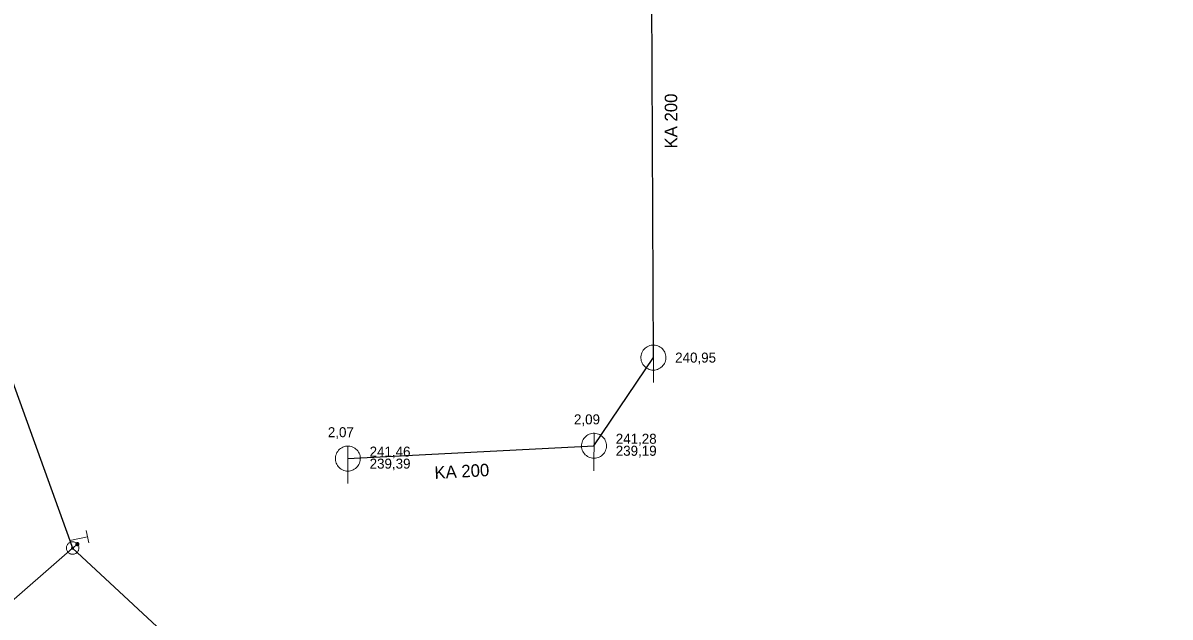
# Model space of a CAD drawing. Extents: x -777996 to -777727, y -976581 to -976199.
# Drawn here: x -777889.9 to -777798.1, y -976473.6 to -976426.1 of the extents above; entities that cross this region are included whole.
import ezdxf

# ---------------------------------------------------------------- set-up
doc = ezdxf.new("R2010")
doc.units = 0
doc.header["$LTSCALE"] = 0.32
doc.linetypes.add('MEDIUM_DASHED', pattern=[4.5, 3, -1.5])
for name, color, linetype, lineweight in [('1', 7, 'MEDIUM_DASHED', 25), ('13', 7, 'Continuous', 13), ('14', 7, 'Continuous', 25), ('17', 7, 'Continuous', 25), ('22', 7, 'Continuous', 13), ('34', 7, 'Continuous', 13), ('47', 7, 'Continuous', 13), ('9', 7, 'Continuous', 13)]:
    doc.layers.add(name, color=color, linetype=linetype, lineweight=lineweight)

msp = doc.modelspace()

# ---------------------------------------------------------------- linework, layer by layer
at = {"layer": '13'}
msp.add_line((-777885.941, -976468.086), (-777917.634, -976495.726), dxfattribs=at)
at = {"layer": '14'}
for p, q in [((-777839.462, -976452.855), (-777839.649, -976413.423)), ((-777844.215, -976459.905), (-777839.462, -976452.855)), ((-777863.916, -976460.934), (-777844.215, -976459.905))]:
    msp.add_line(p, q, dxfattribs=at)
at = {"layer": '14', "lineweight": 13}
for p, q in [((-777886.158, -976467.487), (-777884.76, -976467.18)), ((-777885.941, -976468.086), (-777885.559, -976467.772))]:
    msp.add_line(p, q, dxfattribs=at)
at = {"layer": '17'}
for points in [[(-777908.12, -976394.786), (-777900.403, -976428.079), (-777886.159, -976467.482), (-777885.941, -976468.086)], [(-777885.941, -976468.086), (-777876.204, -976477.129), (-777873.846, -976479.364), (-777871.717, -976481.385), (-777867.989, -976484.745), (-777854.131, -976495.614), (-777828.123, -976517.456), (-777820.88, -976521.51), (-777819.881, -976522.07), (-777768.129, -976539.208), (-777763.26, -976539.92)]]:
    msp.add_lwpolyline(points, dxfattribs=at)
at = {"layer": '22'}
for p, q in [((-777839.462, -976454.855), (-777839.461, -976451.855)), ((-777844.215, -976461.906), (-777844.214, -976458.906)), ((-777863.916, -976462.934), (-777863.915, -976459.934))]:
    msp.add_line(p, q, dxfattribs=at)
for points in [[(-777838.462, -976452.855), (-777838.467, -976452.746), (-777838.485, -976452.638), (-777838.515, -976452.532), (-777838.555, -976452.431), (-777838.607, -976452.334), (-777838.669, -976452.244), (-777838.741, -976452.161), (-777838.821, -976452.087), (-777838.909, -976452.021), (-777839.003, -976451.966), (-777839.103, -976451.921), (-777839.208, -976451.888), (-777839.315, -976451.866), (-777839.424, -976451.856), (-777839.534, -976451.858), (-777839.642, -976451.872), (-777839.749, -976451.897), (-777839.852, -976451.934), (-777839.95, -976451.983), (-777840.042, -976452.041), (-777840.128, -976452.11), (-777840.205, -976452.187), (-777840.274, -976452.273), (-777840.333, -976452.365), (-777840.381, -976452.463), (-777840.418, -976452.566), (-777840.444, -976452.673), (-777840.458, -976452.781), (-777840.461, -976452.891), (-777840.451, -976453), (-777840.43, -976453.107), (-777840.396, -976453.211), (-777840.352, -976453.311), (-777840.297, -976453.406), (-777840.231, -976453.494), (-777840.157, -976453.574), (-777840.074, -976453.646), (-777839.984, -976453.708), (-777839.888, -976453.76), (-777839.786, -976453.801), (-777839.681, -976453.831), (-777839.573, -976453.849), (-777839.463, -976453.855), (-777839.354, -976453.849), (-777839.246, -976453.831), (-777839.141, -976453.802), (-777839.039, -976453.761), (-777838.942, -976453.709), (-777838.852, -976453.647), (-777838.769, -976453.576), (-777838.694, -976453.496), (-777838.629, -976453.408), (-777838.573, -976453.314), (-777838.529, -976453.214), (-777838.495, -976453.11), (-777838.473, -976453.002), (-777838.463, -976452.893)], [(-777843.215, -976459.906), (-777843.22, -976459.797), (-777843.238, -976459.689), (-777843.268, -976459.583), (-777843.308, -976459.482), (-777843.36, -976459.385), (-777843.422, -976459.295), (-777843.494, -976459.212), (-777843.574, -976459.138), (-777843.662, -976459.072), (-777843.756, -976459.017), (-777843.856, -976458.972), (-777843.961, -976458.939), (-777844.068, -976458.917), (-777844.177, -976458.907), (-777844.287, -976458.909), (-777844.395, -976458.923), (-777844.502, -976458.948), (-777844.605, -976458.985), (-777844.703, -976459.034), (-777844.795, -976459.092), (-777844.881, -976459.161), (-777844.958, -976459.238), (-777845.027, -976459.324), (-777845.086, -976459.416), (-777845.134, -976459.514), (-777845.171, -976459.617), (-777845.197, -976459.724), (-777845.211, -976459.832), (-777845.214, -976459.942), (-777845.204, -976460.051), (-777845.183, -976460.158), (-777845.149, -976460.262), (-777845.105, -976460.362), (-777845.05, -976460.457), (-777844.984, -976460.545), (-777844.91, -976460.625), (-777844.827, -976460.697), (-777844.737, -976460.759), (-777844.641, -976460.811), (-777844.539, -976460.852), (-777844.434, -976460.882), (-777844.326, -976460.9), (-777844.216, -976460.906), (-777844.107, -976460.9), (-777843.999, -976460.882), (-777843.894, -976460.853), (-777843.792, -976460.812), (-777843.695, -976460.76), (-777843.605, -976460.698), (-777843.522, -976460.627), (-777843.447, -976460.547), (-777843.382, -976460.459), (-777843.326, -976460.365), (-777843.282, -976460.265), (-777843.248, -976460.161), (-777843.226, -976460.053), (-777843.216, -976459.944)], [(-777862.916, -976460.934), (-777862.921, -976460.825), (-777862.939, -976460.717), (-777862.969, -976460.611), (-777863.009, -976460.51), (-777863.061, -976460.413), (-777863.123, -976460.323), (-777863.195, -976460.24), (-777863.275, -976460.166), (-777863.363, -976460.1), (-777863.457, -976460.045), (-777863.557, -976460), (-777863.662, -976459.967), (-777863.769, -976459.945), (-777863.878, -976459.935), (-777863.988, -976459.937), (-777864.096, -976459.951), (-777864.203, -976459.976), (-777864.306, -976460.013), (-777864.404, -976460.062), (-777864.496, -976460.12), (-777864.582, -976460.189), (-777864.659, -976460.266), (-777864.728, -976460.352), (-777864.787, -976460.444), (-777864.835, -976460.542), (-777864.872, -976460.645), (-777864.898, -976460.752), (-777864.912, -976460.86), (-777864.915, -976460.97), (-777864.905, -976461.079), (-777864.884, -976461.186), (-777864.85, -976461.29), (-777864.806, -976461.39), (-777864.751, -976461.485), (-777864.685, -976461.573), (-777864.611, -976461.653), (-777864.528, -976461.725), (-777864.438, -976461.787), (-777864.342, -976461.839), (-777864.24, -976461.88), (-777864.135, -976461.91), (-777864.027, -976461.928), (-777863.917, -976461.934), (-777863.808, -976461.928), (-777863.7, -976461.91), (-777863.595, -976461.881), (-777863.493, -976461.84), (-777863.396, -976461.788), (-777863.306, -976461.726), (-777863.223, -976461.655), (-777863.148, -976461.575), (-777863.083, -976461.487), (-777863.027, -976461.393), (-777862.983, -976461.293), (-777862.949, -976461.189), (-777862.927, -976461.081), (-777862.917, -976460.972)]]:
    msp.add_lwpolyline(points, close=True, dxfattribs=at)
at = {"layer": '34'}
msp.add_line((-777884.867, -976466.691), (-777884.653, -976467.668), dxfattribs=at)
at = {"layer": '47'}
for points in [[(-777885.767, -976468.555), (-777885.719, -976468.534), (-777885.673, -976468.508), (-777885.631, -976468.478), (-777885.592, -976468.444), (-777885.556, -976468.405), (-777885.525, -976468.363), (-777885.499, -976468.318), (-777885.477, -976468.27), (-777885.46, -976468.221), (-777885.448, -976468.17), (-777885.441, -976468.118), (-777885.442, -976468.065), (-777885.446, -976468.014), (-777885.456, -976467.962), (-777885.471, -976467.912), (-777885.492, -976467.864), (-777885.518, -976467.818), (-777885.549, -976467.775), (-777885.582, -976467.737), (-777885.621, -976467.701), (-777885.663, -976467.67), (-777885.709, -976467.643), (-777885.756, -976467.621), (-777885.805, -976467.604), (-777885.856, -976467.593), (-777885.908, -976467.586), (-777885.961, -976467.586), (-777886.012, -976467.591), (-777886.064, -976467.601), (-777886.114, -976467.616), (-777886.162, -976467.637), (-777886.208, -976467.663), (-777886.251, -976467.693), (-777886.289, -976467.727), (-777886.325, -976467.766), (-777886.357, -976467.807), (-777886.384, -976467.853), (-777886.406, -976467.9), (-777886.422, -976467.95), (-777886.433, -976468.001), (-777886.44, -976468.053), (-777886.441, -976468.105), (-777886.435, -976468.157), (-777886.425, -976468.209), (-777886.41, -976468.259), (-777886.389, -976468.307), (-777886.363, -976468.353), (-777886.334, -976468.395), (-777886.299, -976468.434), (-777886.26, -976468.47), (-777886.219, -976468.502), (-777886.174, -976468.528), (-777886.126, -976468.55), (-777886.076, -976468.566), (-777886.025, -976468.578), (-777885.973, -976468.585), (-777885.921, -976468.585), (-777885.869, -976468.58), (-777885.817, -976468.57)], [(-777885.912, -976468.162), (-777885.904, -976468.159), (-777885.897, -976468.155), (-777885.89, -976468.15), (-777885.884, -976468.144), (-777885.877, -976468.138), (-777885.873, -976468.131), (-777885.868, -976468.124), (-777885.864, -976468.116), (-777885.862, -976468.108), (-777885.86, -976468.099), (-777885.859, -976468.09), (-777885.859, -976468.082), (-777885.86, -976468.074), (-777885.86, -976468.066), (-777885.864, -976468.057), (-777885.867, -976468.049), (-777885.871, -976468.042), (-777885.876, -976468.035), (-777885.882, -976468.029), (-777885.888, -976468.022), (-777885.895, -976468.018), (-777885.902, -976468.013), (-777885.91, -976468.009), (-777885.919, -976468.006), (-777885.927, -976468.005), (-777885.936, -976468.004), (-777885.944, -976468.004), (-777885.952, -976468.005), (-777885.96, -976468.005), (-777885.969, -976468.009), (-777885.977, -976468.012), (-777885.984, -976468.016), (-777885.991, -976468.021), (-777885.997, -976468.027), (-777886.004, -976468.033), (-777886.009, -976468.039), (-777886.013, -976468.047), (-777886.017, -976468.055), (-777886.02, -976468.064), (-777886.021, -976468.072), (-777886.022, -976468.081), (-777886.022, -976468.089), (-777886.021, -976468.097), (-777886.021, -976468.105), (-777886.017, -976468.114), (-777886.014, -976468.122), (-777886.01, -976468.129), (-777886.005, -976468.136), (-777885.999, -976468.142), (-777885.993, -976468.149), (-777885.987, -976468.154), (-777885.979, -976468.158), (-777885.971, -976468.162), (-777885.963, -976468.164), (-777885.954, -976468.166), (-777885.945, -976468.167), (-777885.937, -976468.167), (-777885.929, -976468.166), (-777885.921, -976468.166)]]:
    msp.add_lwpolyline(points, close=True, dxfattribs=at)
at = {"layer": '9'}
for points in [[(-777885.685, -976467.772), (-777885.685, -976467.785), (-777885.683, -976467.798), (-777885.68, -976467.811), (-777885.675, -976467.823), (-777885.669, -976467.835), (-777885.662, -976467.846), (-777885.654, -976467.856), (-777885.644, -976467.866), (-777885.634, -976467.874), (-777885.623, -976467.881), (-777885.611, -976467.887), (-777885.599, -976467.892), (-777885.586, -976467.895), (-777885.573, -976467.897), (-777885.56, -976467.899), (-777885.547, -976467.898), (-777885.534, -976467.896), (-777885.521, -976467.893), (-777885.509, -976467.888), (-777885.497, -976467.882), (-777885.486, -976467.875), (-777885.476, -976467.867), (-777885.466, -976467.857), (-777885.458, -976467.847), (-777885.451, -976467.836), (-777885.445, -976467.824), (-777885.44, -976467.812), (-777885.437, -976467.799), (-777885.435, -976467.786), (-777885.433, -976467.773), (-777885.434, -976467.76), (-777885.436, -976467.747), (-777885.439, -976467.734), (-777885.444, -976467.722), (-777885.45, -976467.71), (-777885.457, -976467.699), (-777885.465, -976467.689), (-777885.475, -976467.679), (-777885.485, -976467.671), (-777885.496, -976467.664), (-777885.508, -976467.658), (-777885.52, -976467.653), (-777885.533, -976467.65), (-777885.546, -976467.648), (-777885.559, -976467.647), (-777885.572, -976467.647), (-777885.585, -976467.649), (-777885.598, -976467.652), (-777885.61, -976467.657), (-777885.622, -976467.663), (-777885.633, -976467.67), (-777885.643, -976467.678), (-777885.653, -976467.688), (-777885.661, -976467.698), (-777885.668, -976467.709), (-777885.674, -976467.721), (-777885.679, -976467.733), (-777885.682, -976467.746), (-777885.684, -976467.759)], [(-777885.665, -976467.772), (-777885.666, -976467.783), (-777885.664, -976467.794), (-777885.661, -976467.805), (-777885.657, -976467.815), (-777885.652, -976467.825), (-777885.646, -976467.834), (-777885.639, -976467.843), (-777885.631, -976467.851), (-777885.622, -976467.858), (-777885.613, -976467.864), (-777885.603, -976467.869), (-777885.593, -976467.873), (-777885.582, -976467.876), (-777885.571, -976467.879), (-777885.56, -976467.879), (-777885.549, -976467.879), (-777885.538, -976467.877), (-777885.527, -976467.874), (-777885.517, -976467.87), (-777885.507, -976467.865), (-777885.498, -976467.859), (-777885.489, -976467.852), (-777885.481, -976467.844), (-777885.474, -976467.835), (-777885.468, -976467.826), (-777885.463, -976467.816), (-777885.459, -976467.806), (-777885.456, -976467.795), (-777885.454, -976467.784), (-777885.453, -976467.773), (-777885.453, -976467.762), (-777885.455, -976467.751), (-777885.458, -976467.74), (-777885.462, -976467.73), (-777885.467, -976467.72), (-777885.473, -976467.711), (-777885.48, -976467.702), (-777885.488, -976467.694), (-777885.497, -976467.687), (-777885.506, -976467.681), (-777885.516, -976467.676), (-777885.526, -976467.672), (-777885.537, -976467.669), (-777885.548, -976467.667), (-777885.559, -976467.667), (-777885.57, -976467.666), (-777885.581, -976467.668), (-777885.592, -976467.671), (-777885.602, -976467.675), (-777885.612, -976467.68), (-777885.621, -976467.686), (-777885.63, -976467.693), (-777885.638, -976467.701), (-777885.645, -976467.71), (-777885.651, -976467.719), (-777885.656, -976467.729), (-777885.66, -976467.739), (-777885.663, -976467.75), (-777885.665, -976467.761)], [(-777885.646, -976467.772), (-777885.646, -976467.781), (-777885.645, -976467.79), (-777885.642, -976467.799), (-777885.639, -976467.807), (-777885.635, -976467.815), (-777885.63, -976467.823), (-777885.624, -976467.83), (-777885.618, -976467.836), (-777885.611, -976467.842), (-777885.603, -976467.847), (-777885.595, -976467.851), (-777885.587, -976467.854), (-777885.578, -976467.857), (-777885.569, -976467.858), (-777885.56, -976467.86), (-777885.551, -976467.859), (-777885.542, -976467.858), (-777885.533, -976467.855), (-777885.525, -976467.852), (-777885.517, -976467.848), (-777885.509, -976467.843), (-777885.502, -976467.837), (-777885.496, -976467.831), (-777885.49, -976467.824), (-777885.485, -976467.816), (-777885.481, -976467.808), (-777885.478, -976467.8), (-777885.475, -976467.791), (-777885.474, -976467.782), (-777885.472, -976467.773), (-777885.473, -976467.764), (-777885.474, -976467.755), (-777885.477, -976467.746), (-777885.48, -976467.738), (-777885.484, -976467.73), (-777885.489, -976467.722), (-777885.495, -976467.715), (-777885.501, -976467.709), (-777885.508, -976467.703), (-777885.516, -976467.698), (-777885.524, -976467.694), (-777885.532, -976467.691), (-777885.541, -976467.688), (-777885.55, -976467.687), (-777885.559, -976467.686), (-777885.568, -976467.686), (-777885.577, -976467.687), (-777885.586, -976467.69), (-777885.594, -976467.693), (-777885.602, -976467.697), (-777885.61, -976467.702), (-777885.617, -976467.708), (-777885.623, -976467.714), (-777885.629, -976467.721), (-777885.634, -976467.729), (-777885.638, -976467.737), (-777885.641, -976467.745), (-777885.644, -976467.754), (-777885.645, -976467.763)], [(-777885.626, -976467.772), (-777885.626, -976467.779), (-777885.625, -976467.786), (-777885.624, -976467.793), (-777885.621, -976467.799), (-777885.618, -976467.805), (-777885.614, -976467.811), (-777885.61, -976467.817), (-777885.605, -976467.822), (-777885.599, -976467.826), (-777885.593, -976467.83), (-777885.587, -976467.833), (-777885.581, -976467.836), (-777885.574, -976467.837), (-777885.567, -976467.84), (-777885.56, -976467.84), (-777885.553, -976467.84), (-777885.546, -976467.838), (-777885.539, -976467.837), (-777885.533, -976467.834), (-777885.526, -976467.831), (-777885.521, -976467.827), (-777885.515, -976467.823), (-777885.51, -976467.818), (-777885.506, -976467.812), (-777885.502, -976467.806), (-777885.499, -976467.8), (-777885.496, -976467.794), (-777885.494, -976467.787), (-777885.493, -976467.78), (-777885.492, -976467.773), (-777885.492, -976467.766), (-777885.493, -976467.759), (-777885.495, -976467.752), (-777885.498, -976467.746), (-777885.501, -976467.739), (-777885.505, -976467.734), (-777885.509, -976467.728), (-777885.514, -976467.723), (-777885.52, -976467.719), (-777885.525, -976467.715), (-777885.532, -976467.712), (-777885.538, -976467.709), (-777885.545, -976467.707), (-777885.552, -976467.706), (-777885.559, -976467.706), (-777885.566, -976467.706), (-777885.573, -976467.706), (-777885.58, -976467.708), (-777885.586, -976467.711), (-777885.592, -976467.714), (-777885.598, -976467.718), (-777885.604, -976467.722), (-777885.609, -976467.727), (-777885.613, -976467.733), (-777885.617, -976467.738), (-777885.62, -976467.745), (-777885.623, -976467.751), (-777885.624, -976467.758), (-777885.626, -976467.765)], [(-777885.606, -976467.772), (-777885.606, -976467.777), (-777885.606, -976467.782), (-777885.605, -976467.787), (-777885.603, -976467.791), (-777885.601, -976467.796), (-777885.598, -976467.8), (-777885.595, -976467.803), (-777885.591, -976467.807), (-777885.588, -976467.81), (-777885.584, -976467.813), (-777885.579, -976467.815), (-777885.575, -976467.817), (-777885.57, -976467.818), (-777885.565, -976467.82), (-777885.56, -976467.82), (-777885.555, -976467.82), (-777885.55, -976467.819), (-777885.545, -976467.818), (-777885.541, -976467.816), (-777885.536, -976467.814), (-777885.532, -976467.811), (-777885.528, -976467.808), (-777885.525, -976467.804), (-777885.522, -976467.801), (-777885.519, -976467.797), (-777885.517, -976467.792), (-777885.515, -976467.788), (-777885.514, -976467.783), (-777885.513, -976467.778), (-777885.512, -976467.773), (-777885.512, -976467.768), (-777885.513, -976467.763), (-777885.514, -976467.758), (-777885.516, -976467.754), (-777885.518, -976467.749), (-777885.521, -976467.745), (-777885.524, -976467.741), (-777885.527, -976467.738), (-777885.531, -976467.735), (-777885.535, -976467.732), (-777885.54, -976467.73), (-777885.544, -976467.728), (-777885.549, -976467.727), (-777885.554, -976467.726), (-777885.559, -976467.726), (-777885.564, -976467.726), (-777885.569, -976467.727), (-777885.574, -976467.727), (-777885.578, -976467.729), (-777885.583, -976467.731), (-777885.587, -976467.734), (-777885.59, -976467.737), (-777885.594, -976467.74), (-777885.597, -976467.744), (-777885.6, -976467.748), (-777885.602, -976467.753), (-777885.604, -976467.757), (-777885.605, -976467.762), (-777885.606, -976467.767)], [(-777885.586, -976467.772), (-777885.586, -976467.775), (-777885.587, -976467.778), (-777885.586, -976467.78), (-777885.585, -976467.783), (-777885.584, -976467.786), (-777885.582, -976467.788), (-777885.58, -976467.79), (-777885.578, -976467.792), (-777885.576, -976467.794), (-777885.574, -976467.796), (-777885.571, -976467.798), (-777885.568, -976467.799), (-777885.566, -976467.799), (-777885.563, -976467.8), (-777885.56, -976467.8), (-777885.557, -976467.8), (-777885.554, -976467.8), (-777885.551, -976467.799), (-777885.549, -976467.798), (-777885.546, -976467.797), (-777885.544, -976467.795), (-777885.541, -976467.793), (-777885.539, -976467.791), (-777885.538, -976467.789), (-777885.536, -976467.787), (-777885.535, -976467.784), (-777885.533, -976467.781), (-777885.533, -976467.779), (-777885.532, -976467.776), (-777885.531, -976467.773), (-777885.532, -976467.77), (-777885.532, -976467.767), (-777885.533, -976467.764), (-777885.534, -976467.762), (-777885.535, -976467.759), (-777885.537, -976467.757), (-777885.538, -976467.754), (-777885.54, -976467.752), (-777885.543, -976467.751), (-777885.545, -976467.749), (-777885.548, -976467.748), (-777885.55, -976467.747), (-777885.553, -976467.746), (-777885.556, -976467.746), (-777885.559, -976467.745), (-777885.562, -976467.746), (-777885.565, -976467.745), (-777885.567, -976467.747), (-777885.57, -976467.747), (-777885.573, -976467.748), (-777885.575, -976467.75), (-777885.577, -976467.751), (-777885.579, -976467.753), (-777885.581, -976467.756), (-777885.583, -976467.758), (-777885.584, -976467.761), (-777885.585, -976467.763), (-777885.586, -976467.766), (-777885.586, -976467.769)], [(-777885.567, -976467.772), (-777885.567, -976467.774), (-777885.567, -976467.774), (-777885.566, -976467.774), (-777885.566, -976467.776), (-777885.567, -976467.777), (-777885.565, -976467.777), (-777885.565, -976467.777), (-777885.565, -976467.779), (-777885.565, -976467.779), (-777885.564, -976467.78), (-777885.562, -976467.78), (-777885.562, -976467.78), (-777885.562, -976467.781), (-777885.56, -976467.781), (-777885.56, -976467.781), (-777885.559, -976467.781), (-777885.558, -976467.781), (-777885.558, -976467.78), (-777885.557, -976467.78), (-777885.555, -976467.78), (-777885.555, -976467.779), (-777885.555, -976467.779), (-777885.554, -976467.778), (-777885.554, -976467.778), (-777885.552, -976467.777), (-777885.552, -976467.776), (-777885.551, -976467.775), (-777885.551, -976467.775), (-777885.551, -976467.774), (-777885.551, -976467.773), (-777885.551, -976467.772), (-777885.551, -976467.771), (-777885.551, -976467.771), (-777885.552, -976467.77), (-777885.552, -976467.769), (-777885.553, -976467.768), (-777885.553, -976467.768), (-777885.554, -976467.767), (-777885.554, -976467.767), (-777885.555, -976467.766), (-777885.556, -976467.766), (-777885.557, -976467.765), (-777885.557, -976467.765), (-777885.558, -976467.765), (-777885.559, -976467.765), (-777885.56, -976467.765), (-777885.561, -976467.765), (-777885.561, -976467.765), (-777885.562, -976467.766), (-777885.563, -976467.765), (-777885.564, -976467.767), (-777885.564, -976467.767), (-777885.565, -976467.767), (-777885.565, -976467.767), (-777885.566, -976467.769), (-777885.566, -976467.77), (-777885.566, -976467.771), (-777885.567, -976467.771), (-777885.567, -976467.772)]]:
    msp.add_lwpolyline(points, close=True, dxfattribs=at)

# ---------------------------------------------------------------- texts
at = {"layer": '1'}
for rotation, p in [(90, (-777837.555, -976436.129)), (3, (-777856.957, -976462.558))]:
    msp.add_text('KA 200', height=1, rotation=rotation, dxfattribs=at).set_placement(p)
for s, p in [('240,95', (-777837.719, -976453.254)), ('2,09', (-777845.815, -976458.194)), ('2,07', (-777865.516, -976459.222))]:
    msp.add_text(s, height=0.8, dxfattribs=at).set_placement(p)
at = {"layer": '22'}
for s, p in [('241,28', (-777842.472, -976459.746)), ('241,46', (-777862.173, -976460.774)), ('239,19', (-777842.472, -976460.706)), ('239,39', (-777862.173, -976461.734))]:
    msp.add_text(s, height=0.8, dxfattribs=at).set_placement(p)

doc.saveas('drawing.dxf')
